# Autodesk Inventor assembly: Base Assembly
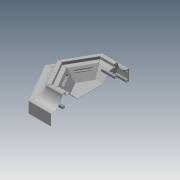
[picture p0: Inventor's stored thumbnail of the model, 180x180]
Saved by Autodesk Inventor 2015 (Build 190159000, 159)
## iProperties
Created: 2014-12
Part Number: Base Assembly
Document SubType Name: Assembly
Designer: rsheridan
Author: rsheridan
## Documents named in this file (5)
- C:\Users\TREINA6\Desktop\#46- Sheet Metal Technology\WSC2015_TP46_pre\Sheet Metal\Base Assembly.iam
- C:\Users\TREINA6\Desktop\#46- Sheet Metal Technology\WSC2015_TP46_pre\Sheet Metal\Outer Base.iam
- C:\Users\TREINA6\Desktop\#46- Sheet Metal Technology\WSC2015_TP46_pre\Sheet Metal\Fire Tray.ipt
- C:\Users\TREINA6\Desktop\#46- Sheet Metal Technology\WSC2015_TP46_pre\Sheet Metal\Base Assembly\Design Accelerator\Bolted Connection1.iam
- C:\Users\TREINA6\Desktop\#46- Sheet Metal Technology\WSC2015_TP46_pre\Sheet Metal\Base Assembly\Base Frame\Base Frame.iam
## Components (4 placed, 4 different names)
1. Outer Base:1 [sub-assembly] — Mate:1, Mate:2, Mate:5, Mate:6, Flush:1, Mate:9, Mate:10, Angle:1
2. Fire Tray:1 — Mate:5, Mate:6, Flush:1, Mate:7, Mate:8
3. Bolted Connection:1 [sub-assembly] — Mate:7, Mate:8
4. Base Frame:1 [sub-assembly] — Mate:9, Mate:10, Angle:1
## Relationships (10: Mate 8, Flush 1, Angle 1)
- Mate:1: Outer Base:1
- Mate:2: Outer Base:1
- Mate:5: Outer Base:1 ↔ Fire Tray:1
- Mate:6: Outer Base:1 ↔ Fire Tray:1
- Flush:1: Outer Base:1 ↔ Fire Tray:1
- Mate:7: Fire Tray:1 ↔ Bolted Connection:1
- Mate:8: Fire Tray:1 ↔ Bolted Connection:1
- Mate:9: Outer Base:1 ↔ Base Frame:1
- Mate:10: Outer Base:1 ↔ Base Frame:1
- Angle:1: Outer Base:1 ↔ Base Frame:1
